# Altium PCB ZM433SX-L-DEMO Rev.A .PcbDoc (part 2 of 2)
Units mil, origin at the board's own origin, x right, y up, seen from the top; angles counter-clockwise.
Board outline 3937.01 x 2559.06 mil, 2 copper layers (Top Layer, Bottom Layer); 88 components, 121 nets, 406 pads, 438 vias.
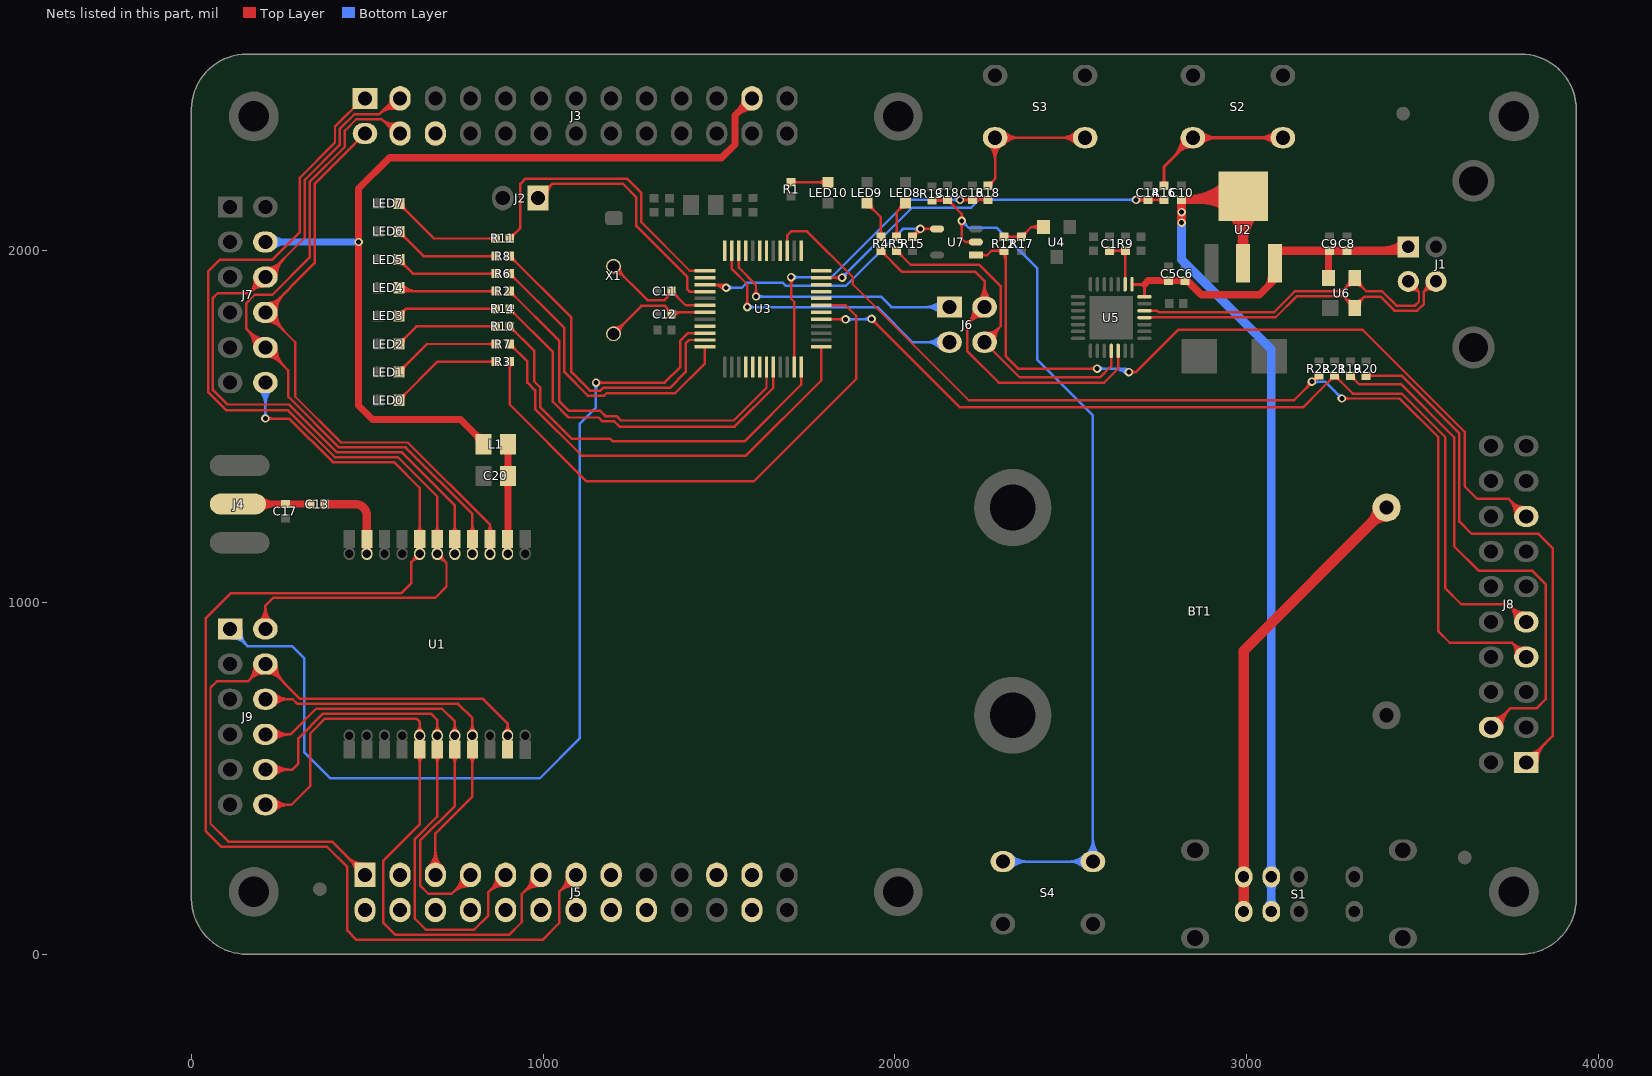
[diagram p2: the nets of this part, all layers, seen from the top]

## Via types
v1: diameter 24, hole 14, Top Layer to Bottom Layer, tented both sides, 426 vias
v2: diameter 20, hole 12, Top Layer to Bottom Layer, tented both sides, 7 vias
v3: diameter 24, hole 14, Top Layer to Bottom Layer, tented bottom, 5 vias

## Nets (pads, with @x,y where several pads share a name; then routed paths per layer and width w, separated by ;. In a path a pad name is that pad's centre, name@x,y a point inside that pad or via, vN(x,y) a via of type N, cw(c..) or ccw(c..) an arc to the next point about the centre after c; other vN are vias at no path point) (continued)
ESEL: J9.1 U3.10 | length 3069.9
  Top Layer w7: v1(1150,1624.91) 1345,1624.91 1390,1669.91 1390,1744.91 1411.1,1766.01 U3.10@1459.65,1766.01 ; v1@1156.01,1618.9 cw(c1170.52,1604.39) 1170.52,1624.91 cw(c1170.52,1645.43) v1@1156.01,1630.92
  Bottom Layer w7: J9.1@110,924.91 159,875.91 286,875.91 320,841.91 320,574.91 395,499.91 990,499.91 1104.5,614.41 1104.5,1508.41 1150,1553.91 v1(1150,1624.91) ; J9.1@115,898.41 cw(c115,846.5) 151.7,883.2 ; J9.1@115,905.41 cw(c115,870.4) J9.1@139.75,895.15 ; J9.1@127.47,924.01 ccw(c161.33,921.59) J9.1@137.32,897.58 ; J9.1@134.45,923.51 ccw(c181.55,920.14) 148.16,886.75 ; J9.1@141.43,923.01 ccw(c201.78,918.69) 159,875.91 ; v1@1143.99,1618.9 cw(c1129.48,1604.39) 1150,1604.39 cw(c1170.52,1604.39) v1@1156.01,1618.9
GPIO1_17: J5.14
GPIO1_18: J5.13 J7.12 U1.18 | length 4089.4
  Top Layer w7: v1(210,1523.03) 277.68,1523.03 401.8,1398.91 576,1398.91 648.72,1326.18 U1.18@648.72,1180.18 ; v1@216.01,1517.02 cw(c230.52,1502.51) 230.52,1523.03 cw(c230.52,1543.55) v1@216.01,1529.04 ; 628.8,1118.92 ccw(c610.87,1136.85) U1.18@636.22,1136.85 ; 636.43,1126.55 cw(c648.03,1114.96) U1.18@648.55,1131.35 ; U1.18@639.88,1198.61 ccw(c618.55,1219.95) 648.72,1219.95 ccw(c678.9,1219.95) U1.18@657.56,1198.61 ; U1.18@648.33,1124.35 ccw(c647.32,1092.81) 625,1115.12 ; U1.18@648.72,1138.85 625,1115.12 ; 1051.61,183.97 ccw(c1014.9,220.67) J5.13@1066.81,220.67 ; 1055.68,188.04 cw(c1087.92,155.8) J5.13@1091.69,201.24 ; 1063.56,195.92 ccw(c1038.8,220.67) J5.13@1073.81,220.67 ; 1066.35,198.72 cw(c1089.56,175.51) J5.13@1092.27,208.21 ; J5.13@1091.11,194.26 ccw(c1086.28,136.09) 1045,177.36 ; J5.13@1093.31,225.67 1045,177.36 ; 625,1115.12 625,1054.91 596.97,1026.88 111.97,1026.88 40,954.91 40,349.91 85,304.91 386,304.91 443,247.91 443,66.91 469,40.91 998,40.91 1045,87.91 1045,177.36
  Bottom Layer w7: J7.12@191.26,1606.17 cw(c146.02,1560.93) 210,1560.93 cw(c273.98,1560.93) J7.12@228.74,1606.17 ; J7.12@196.21,1611.12 cw(c162.92,1577.83) 210,1577.83 cw(c257.08,1577.83) J7.12@223.79,1611.12 ; J7.12@201.16,1616.07 cw(c179.82,1594.73) 210,1594.73 cw(c240.18,1594.73) J7.12@218.84,1616.07 ; v1@203.99,1529.04 ccw(c189.48,1543.55) 210,1543.55 ccw(c230.52,1543.55) v1@216.01,1529.04 ; v1(210,1523.03) J7.12@210,1624.91
GPIO2_4: J5.12
GPIO2_5: J5.11 J9.12 U1.5 | length 2310.9
  Top Layer w7: J9.12@210,424.91 284,424.91 337.5,478.41 337.5,627.41 380,669.91 640,669.91 648.72,661.18 U1.5@648.72,620.97 ; J9.12@223.84,416.07 cw(c245.18,394.73) 245.18,424.91 cw(c245.18,455.08) J9.12@223.84,433.75 ; J9.12@228.79,411.12 cw(c262.08,377.83) 262.08,424.91 cw(c262.08,471.98) J9.12@228.79,438.7 ; J9.12@233.74,406.17 cw(c278.98,360.93) 278.98,424.91 cw(c278.98,488.88) J9.12@233.74,443.65 ; U1.5@639.88,563.19 cw(c618.55,541.85) 648.72,541.85 cw(c678.9,541.85) U1.5@657.56,563.19 ; U1.5@639.88,631.81 ccw(c618.55,653.15) 648.72,653.15 ccw(c678.9,653.15) U1.5@657.56,631.81 ; U1.5@648.72,581.62 648.72,368.63 545,264.91 545,89.91 580,54.91 903,54.91 939,90.91 939,171.36 J5.11@993.31,225.67 ; 939.54,171.9 cw(c993.31,118.12) J5.11@993.31,194.17 ; 951.48,183.85 cw(c993.31,142.02) J5.11@993.31,201.17 ; 951.61,183.97 ccw(c914.9,220.67) J5.11@966.81,220.67 ; 963.43,195.8 cw(c993.31,165.92) J5.11@993.31,208.17 ; 963.56,195.92 ccw(c938.8,220.67) J5.11@973.81,220.67
GPIO2_6: J5.10
GPIO2_7: J5.9 J9.10 U1.6 | length 2038.4
  Top Layer w7: J9.10@210,524.91 287,524.91 304,541.91 304,613.71 374.2,683.91 681,683.91 698.72,666.18 U1.6@698.72,620.97 ; J9.10@223.84,516.07 cw(c245.18,494.73) 245.18,524.91 cw(c245.18,555.08) J9.10@223.84,533.75 ; J9.10@228.79,511.12 cw(c262.08,477.83) 262.08,524.91 cw(c262.08,571.98) J9.10@228.79,538.7 ; J9.10@233.74,506.17 cw(c278.98,460.93) 278.98,524.91 cw(c278.98,588.88) J9.10@233.74,543.65 ; U1.6@689.88,563.19 cw(c668.55,541.85) 698.72,541.85 cw(c728.9,541.85) U1.6@707.56,563.19 ; U1.6@689.88,631.81 ccw(c668.55,653.15) 698.72,653.15 ccw(c728.9,653.15) U1.6@707.56,631.81 ; U1.6@698.72,581.62 698.72,391.43 635,327.71 635,100.91 666,69.91 804,69.91 844,109.91 844,176.36 ; 851.61,183.97 ccw(c814.9,220.67) J5.9@866.81,220.67 ; 854.91,187.27 cw(c888.82,153.36) J5.9@892.01,201.21 ; 863.56,195.92 ccw(c838.8,220.67) J5.9@873.81,220.67 ; 865.82,198.18 cw(c890.19,173.81) J5.9@892.48,208.2 ; J5.9@891.55,194.23 ccw(c887.46,132.91) 844,176.36 ; J5.9@893.31,225.67 844,176.36
GPIO2_12: J5.8
GPIO2_13: J5.7 J9.8 U1.7 | length 1751.3
  Top Layer w7: J9.8@210,624.91 281,624.91 354,697.91 712,697.91 748.72,661.18 U1.7@748.72,620.97 ; J9.8@223.84,616.07 cw(c245.18,594.73) 245.18,624.91 cw(c245.18,655.08) J9.8@223.84,633.75 ; J9.8@228.79,611.12 cw(c262.08,577.83) 262.08,624.91 cw(c262.08,671.98) J9.8@228.79,638.7 ; J9.8@233.74,606.17 cw(c278.98,560.93) 278.98,624.91 cw(c278.98,688.88) J9.8@233.74,643.65 ; U1.7@739.88,563.19 cw(c718.55,541.85) 748.72,541.85 cw(c778.9,541.85) U1.7@757.56,563.19 ; U1.7@739.88,631.81 ccw(c718.55,653.15) 748.72,653.15 ccw(c778.9,653.15) U1.7@757.56,631.81 ; U1.7@748.72,581.62 748.72,421.63 650,322.91 650,194.91 673,171.91 739.55,171.91 ; 751.49,183.86 cw(c793.3,142.06) J5.7@793.31,201.17 ; 751.61,183.97 ccw(c714.9,220.67) J5.7@766.81,220.67 ; 763.44,195.8 cw(c793.3,165.94) J5.7@793.31,208.17 ; 763.56,195.92 ccw(c738.8,220.67) J5.7@773.81,220.67 ; J5.7@793.3,194.17 ccw(c793.29,118.17) 739.55,171.91 ; J5.7@793.31,225.67 739.55,171.91
GPIO2_14: J5.6
GPIO2_15: J5.5 J9.6 U1.8 | length 1599.3
  Top Layer w7: J9.6@210,724.91 288,724.91 301,711.91 758,711.91 798.72,671.18 U1.8@798.72,620.97 ; J9.6@223.84,716.07 cw(c245.18,694.73) 245.18,724.91 cw(c245.18,755.08) J9.6@223.84,733.75 ; J9.6@228.79,711.12 cw(c262.08,677.83) 262.08,724.91 cw(c262.08,771.98) J9.6@228.79,738.7 ; J9.6@233.74,706.17 cw(c278.98,660.93) 278.98,724.91 cw(c278.98,788.88) J9.6@233.74,743.65 ; J5.5@674.57,249.41 ccw(c629.33,294.65) 693.31,294.65 ccw(c757.29,294.65) J5.5@712.05,249.41 ; J5.5@679.52,244.46 ccw(c646.23,277.75) 693.31,277.75 ccw(c740.39,277.75) J5.5@707.1,244.46 ; J5.5@684.47,239.51 ccw(c663.13,260.85) 693.31,260.85 ccw(c723.49,260.85) J5.5@702.15,239.51 ; J5.5@693.31,225.67 693.31,343.22 798.72,448.63 U1.8@798.72,581.62 ; U1.8@789.88,563.19 cw(c768.55,541.85) 798.72,541.85 cw(c828.9,541.85) U1.8@807.56,563.19 ; U1.8@789.88,631.81 ccw(c768.55,653.15) 798.72,653.15 ccw(c828.9,653.15) U1.8@807.56,631.81
GPIO3_20: J5.4
GPIO3_21: J5.3
GPIO3_26: J5.2
GPIO3_27: J5.1 J9.4 U1.10 | length 2516.4
  Top Layer w7: 168.3,783.2 cw(c205,746.5) J9.4@205,798.41 ; 171.84,786.75 ccw(c138.45,820.14) J9.4@185.55,823.51 ; J9.4@178.57,823.01 cw(c118.22,818.69) 161,775.91 ; 180.25,795.15 cw(c205,770.4) J9.4@205,805.41 ; 182.68,797.58 ccw(c158.67,821.59) J9.4@192.53,824.01 ; J9.4@215,798.41 cw(c215,746.5) 251.7,783.2 ; J9.4@215,805.41 cw(c215,770.4) 239.75,795.15 ; J9.4@227.5,824.91 ccw(c269.75,824.91) 239.87,795.03 ; J9.4@234.5,824.91 ccw(c293.65,824.91) 251.82,783.08 ; J9.4@241.5,824.91 ccw(c317.55,824.91) 263.77,771.13 ; 439.54,279.44 ccw(c493.31,333.22) J5.1@493.31,257.17 ; 451.48,267.49 ccw(c493.31,309.32) J5.1@493.31,250.17 ; 451.61,267.37 cw(c414.9,230.67) J5.1@466.81,230.67 ; J5.1@463.43,255.54 ccw(c493.31,285.42) J5.1@493.31,243.17 ; J5.1@463.56,255.42 cw(c438.8,230.67) J5.1@473.81,230.67 ; J5.1@493.31,225.67 399.07,319.91 105,319.91 54,370.91 54,757.91 72,775.91 161,775.91 ; U1.10@889.88,631.81 ccw(c868.55,653.15) 898.72,653.15 ccw(c928.9,653.15) U1.10@907.56,631.81 ; U1.10@898.72,620.97 898.72,656.18 829,725.91 309,725.91 J9.4@210,824.91 161,775.91
HPL: J5.24
HPR: J5.23
HSADC: J5.18
I2C0_SCL: J5.15
I2C0_SDA: J5.16
J_NRST: J8.15 R12.1 U7.1 | length 2723.4
  Top Layer w7: U7.1@2230,1987.51 2262.6,1987.51 2275,1999.91 R12.1@2310,1999.91 2314.5,1995.41 2314.5,1700.41 2350,1664.91 v1(2575,1664.91) ; U7.1@2244.6,1982.91 cw(c2255.69,1971.81) 2255.69,1987.51 cw(c2255.69,2003.2) U7.1@2244.6,1992.1 ; R12.1@2303.14,1994.03 ccw(c2288.95,1979.84) 2288.95,1999.91 ccw(c2288.95,2019.97) R12.1@2303.14,2005.78 ; R12.1@2305.11,1994.03 cw(c2282.43,1971.35) 2314.5,1971.35 ; R12.1@2310.06,1998.98 cw(c2299.33,1988.25) R12.1@2314.5,1988.25 ; R12.1@2314.5,1988.33 cw(c2322.56,1988.33) R12.1@2316.86,1994.03 ; v1@2568.99,1658.9 ccw(c2554.48,1644.39) 2554.48,1664.91 ccw(c2554.48,1685.43) v1@2568.99,1670.92 ; v1(2665,1654.91) 2685,1654.91 ; v1@2671.12,1649.01 cw(c2685,1635.63) 2685,1654.91 ; v1@2671.12,1660.81 ccw(c2685,1674.18) 2685,1654.91 ; 3753.3,1286.61 ccw(c3790,1323.31) J8.15@3790,1271.41 ; 3756.07,1283.84 cw(c3720.98,1248.75) J8.15@3770.53,1245.99 ; J8.15@3763.54,1246.38 ccw(c3700.01,1249.91) 3745,1294.9 ; 3765.25,1274.66 ccw(c3790,1299.41) J8.15@3790,1264.41 ; 3767.14,1272.77 cw(c3741.95,1247.58) J8.15@3777.52,1245.6 ; J8.15@3795,1244.91 3745,1294.91 ; 2685,1654.91 2805,1774.91 3330,1774.91 3620,1484.91 3620,1329.91 3655,1294.91 3745,1294.91
  Bottom Layer w7: v1(2575,1664.91) 2655,1664.91 v1(2665,1654.91) ; v1@2581.01,1658.9 cw(c2595.52,1644.39) 2595.52,1664.91 cw(c2595.52,1685.43) v1@2581.01,1670.92 ; 2620.34,1664.91 cw(c2620.34,1610.24) v1@2658.99,1648.9 ; 2637.24,1664.91 cw(c2637.24,1627.14) v1@2663.94,1653.85 ; 2654.14,1664.91 cw(c2654.14,1644.04) v1@2668.89,1658.8
MIC: J5.21
NetC1_2: C1.2 R9.1 U5.9 | length 235.3
  Top Layer w7: C1.2@2610,1999.91 R9.1@2655,1999.91 2654.37,1999.28 U5.9@2654.37,1904.4 ; C1.2@2616.86,1994.03 cw(c2631.05,1979.84) 2631.05,1999.91 cw(c2631.05,2019.97) C1.2@2616.86,2005.78 ; R9.1@2648.14,2005.78 cw(c2633.95,2019.97) 2633.95,1999.91 cw(c2633.95,1979.84) 2648.14,1994.03 cw(c2633.1,1978.99) 2654.37,1978.99 ; 2654.37,1980.7 cw(c2673.22,1980.7) R9.1@2659.89,1994.03
NetC13_1: C13.1 U1.21 | length 247.3
  Top Layer w24: C13.1@378,1279.91 465,1279.91 cw(c465,1246.18) 498.72,1246.18 U1.21@498.72,1180.18 U1.21@498.72,1138.85
NetC13_2: C13.2 C17.1 J4.1 | length 282.5
  Top Layer w20: J4.1@132,1279.91 C17.1@267,1279.91 C13.2@338.63,1279.91 ; J4.1@196.14,1265.76 cw(c230.28,1231.62) 230.28,1279.91 cw(c230.28,1328.19) J4.1@196.14,1294.05
NetC18_1: C18.1 R13.2 S4.2 S4.3 U7.2 | length 3376.8
  Top Layer w7: R13.2@2105,2142.67 C18.1@2152.24,2142.67 ; R13.2@2111.86,2136.79 cw(c2126.05,2122.61) 2126.05,2142.67 cw(c2126.05,2162.74) R13.2@2111.86,2148.55 ; 2123.55,2142.67 ccw(c2123.55,2170.37) C18.1@2143.14,2150.78 ; 2134.35,2142.67 cw(c2134.35,2130.24) C18.1@2143.14,2139.03 ; C18.1@2150,2144.91 C18.1@2152.24,2142.67 ; C18.1@2150.98,2136.6 cw(c2150.98,2118.91) 2163.49,2131.42 ; C18.1@2159.3,2144.91 ccw(c2181.74,2144.91) 2165.87,2129.04 ; v1@2183.99,2078.9 cw(c2169.48,2064.39) 2190,2064.39 cw(c2210.52,2064.39) v1@2196.01,2078.9 ; v1@2184.1,2091.03 ccw(c2170.72,2104.91) 2190,2104.91 ; v1@2195.9,2091.03 cw(c2209.28,2104.91) 2190,2104.91 ; U7.2@2215.4,2020.31 ccw(c2204.31,2009.22) 2204.31,2024.91 ccw(c2204.31,2040.6) U7.2@2215.4,2029.5 ; U7.2@2230,2024.91 2200,2024.91 2190,2034.91 v1(2190,2084.91) 2190,2104.91 ; C18.1@2152.24,2142.67 2190,2104.91
  Bottom Layer w7: v1@2190,2076.41 cw(c2190,2055.89) 2204.51,2070.4 cw(c2219.02,2084.91) v1@2198.5,2084.91 ; v1(2190,2084.91) 2210,2064.91 2290,2064.91 2405,1949.91 2405,1689.91 2562.95,1531.95 S4.2@2562.95,263.49 S4.3@2307.05,263.49 ; S4.3@2320.89,254.65 cw(c2342.22,233.31) 2342.22,263.49 cw(c2342.22,293.67) S4.3@2320.89,272.33 ; S4.3@2325.84,249.7 cw(c2359.12,216.41) 2359.12,263.49 cw(c2359.12,310.57) S4.3@2325.84,277.28 ; S4.3@2330.79,244.75 cw(c2376.02,199.51) 2376.02,263.49 cw(c2376.02,327.47) S4.3@2330.79,282.23 ; S4.2@2539.21,244.75 ccw(c2493.98,199.51) 2493.98,263.49 ccw(c2493.98,327.47) S4.2@2539.21,282.23 ; S4.2@2544.16,249.7 ccw(c2510.88,216.41) 2510.88,263.49 ccw(c2510.88,310.57) S4.2@2544.16,277.28 ; S4.2@2544.21,282.23 ccw(c2498.98,327.47) 2562.95,327.47 ccw(c2626.93,327.47) S4.2@2581.69,282.23 ; S4.2@2549.11,254.65 ccw(c2527.78,233.31) 2527.78,263.49 ccw(c2527.78,293.67) S4.2@2549.11,272.33 ; S4.2@2549.16,277.28 ccw(c2515.88,310.57) 2562.95,310.57 ccw(c2610.03,310.57) S4.2@2576.74,277.28 ; S4.2@2554.11,272.33 ccw(c2532.78,293.67) 2562.95,293.67 ccw(c2593.13,293.67) S4.2@2571.79,272.33
NetC20_1: C20.1 L1.1 U1.13 | length 499.8
  Top Layer w20: C20.1@891.06,1345.07 cw(c869.49,1323.49) 900,1323.49 cw(c930.51,1323.49) C20.1@908.94,1345.07 ; C20.1@891.06,1374.75 ccw(c869.49,1396.32) 900,1396.32 ccw(c930.51,1396.32) C20.1@908.94,1374.75 ; L1.1@891.06,1435.07 cw(c869.49,1413.49) 900,1413.49 cw(c930.51,1413.49) L1.1@908.94,1435.07 ; U1.13@894.48,1145.09 ccw(c881.16,1158.41) U1.13@900,1158.41 ; U1.13@894.48,1166.35 cw(c881.16,1153.03) U1.13@900,1153.03 ; U1.13@894.48,1194.02 ccw(c881.16,1207.34) 900,1207.34 ; U1.13@898.72,1138.85 900,1140.12 C20.1@900,1359.91 L1.1@900,1449.91
NetJ1_2: J1.2 U5.5 U6.3 | length 1165.9
  Top Layer w7: U5.5@2709.49,1829.59 2745.31,1829.59 2750,1824.91 3076.92,1824.91 3136.92,1884.91 3269.5,1884.91 U6.3@3307.5,1922.91 3307.5,1917.41 3340,1884.91 3384.8,1884.91 3425.8,1843.91 3479,1843.91 3490,1854.91 3490,1882.27 J1.2@3459.57,1912.7 ; 3274.21,1889.62 cw(c3307.5,1856.33) 3307.5,1903.41 cw(c3307.5,1869.61) 3331.4,1893.51 ; 3286.16,1901.57 cw(c3307.5,1880.23) U6.3@3307.5,1910.41 ; 3286.28,1901.69 ccw(c3270.06,1917.91) U6.3@3293,1917.91 ; U6.3@3315,1917.91 ccw(c3334.31,1917.91) U6.3@3320.66,1904.25 ; U6.3@3322,1917.91 ccw(c3358.21,1917.91) 3332.61,1892.3 ; J1.2@3465.67,1894.18 cw(c3470.67,1879.02) 3481.96,1890.31 cw(c3493.25,1901.6) J1.2@3478.09,1906.6 ; J1.2@3467.86,1887.53 cw(c3474.66,1866.93) 3490,1882.27 cw(c3505.34,1897.61) J1.2@3484.73,1904.41
NetJ1_3: J1.3 U5.4 U6.2 | length 1200.5
  Top Layer w7: U5.4@2709.49,1809.91 2710.49,1810.91 3082.72,1810.91 3142.72,1870.91 3274,1870.91 U6.2@3307.5,1837.41 ; U5.4@2726.24,1808.9 cw(c2731.08,1804.06) 2731.08,1810.91 ; 3275.06,1869.84 ccw(c3307.5,1902.28) 3307.5,1856.41 ccw(c3307.5,1890.21) 3331.4,1866.31 ; 3285.93,1858.98 cw(c3268.86,1841.91) U6.2@3293,1841.91 ; 3287.01,1857.89 ccw(c3307.5,1878.38) U6.2@3307.5,1849.41 ; U6.2@3307.5,1836.91 U6.2@3307.5,1837.41 ; U6.2@3315,1841.91 cw(c3334.31,1841.91) U6.2@3320.66,1855.56 ; U6.2@3322,1841.91 cw(c3358.21,1841.91) 3332.61,1867.51 ; 3511.27,1891.17 cw(c3523.57,1878.87) J1.3@3530.52,1894.82 ; J1.3@3512.11,1908.68 cw(c3483.61,1904.3) 3504,1883.91 ; 3513.77,1893.68 ccw(c3500.55,1906.9) J1.3@3519.03,1909.74 ; J1.3@3527.73,1888.41 ccw(c3519.17,1868.74) 3504,1883.91 ; J1.3@3538.31,1912.7 3532.8,1912.7 3504,1883.91 ; U6.2@3307.5,1837.41 3307.5,1842.41 3335,1869.91 3380,1869.91 3420,1829.91 3485,1829.91 3504,1848.91 3504,1883.91
NetJ8_4: J8.4 R19.2 | length 1736.7
  Top Layer w7: R19.2@3295,1644.91 3320,1619.91 3440,1619.91 3590,1469.91 3590,1159.91 3659.5,1090.41 3811.78,1090.41 3850,1052.18 3850,724.91 3825,699.91 3750,699.91 J8.4@3695,644.91 ; R19.2@3295.98,1636.6 cw(c3295.98,1618.91) 3308.49,1631.42 ; R19.2@3304.3,1644.91 ccw(c3326.74,1644.91) 3310.87,1629.04 ; J8.4@3700,664.41 ccw(c3700,699.41) 3724.75,674.66 ; J8.4@3700,671.41 ccw(c3700,723.31) 3736.7,686.61 ; J8.4@3712.5,644.91 cw(c3754.75,644.91) 3724.87,674.78 ; J8.4@3719.5,644.91 cw(c3778.65,644.91) 3736.82,686.73 ; J8.4@3726.5,644.91 cw(c3802.55,644.91) 3748.77,698.68
NetLED0_2: LED0.2 R3.1 | length 399
  Top Layer w7: LED0.2@589.53,1574.91 699.53,1684.91 R3.1@865,1684.91 ; LED0.2@589.53,1587.15 ccw(c589.53,1616.72) 610.44,1595.82 ccw(c631.34,1574.91) LED0.2@601.78,1574.91 ; R3.1@859.12,1679.03 ccw(c844.94,1664.84) 844.94,1684.91 ccw(c844.94,1704.97) R3.1@859.12,1690.78
NetLED1_2: LED1.2 R7.2 | length 386.6
  Top Layer w7: LED1.2@589.53,1654.91 669.53,1734.91 R7.2@865,1734.91 ; LED1.2@589.53,1667.15 ccw(c589.53,1696.72) 610.44,1675.82 ccw(c631.34,1654.91) LED1.2@601.78,1654.91 ; R7.2@859.12,1729.03 ccw(c844.94,1714.84) 844.94,1734.91 ccw(c844.94,1754.97) R7.2@859.12,1740.78
NetLED2_2: LED2.2 R10.2 | length 374.1
  Top Layer w7: LED2.2@589.53,1734.91 639.53,1784.91 R10.2@865,1784.91 ; LED2.2@589.53,1747.15 ccw(c589.53,1776.72) 610.44,1755.82 ccw(c631.34,1734.91) LED2.2@601.78,1734.91 ; R10.2@859.12,1779.03 ccw(c844.94,1764.84) 844.94,1784.91 ccw(c844.94,1804.97) R10.2@859.12,1790.78
NetLED3_2: LED3.2 R14.2 | length 358.6
  Top Layer w7: LED3.2@589.53,1814.91 609.53,1834.91 ; LED3.2@589.92,1827.15 ccw(c590.77,1853.67) 609.53,1834.91 ; LED3.2@601.77,1815.3 cw(c628.29,1816.15) 609.53,1834.91 ; R14.2@859.12,1829.03 ccw(c844.94,1814.84) 844.94,1834.91 ccw(c844.94,1854.97) R14.2@859.12,1840.78 ; R14.2@865,1834.91 609.53,1834.91
NetLED4_2: LED4.2 R2.1 | length 421.4
  Top Layer w7: LED4.2@588.29,1893.67 ccw(c609.44,1914.82) 609.44,1884.91 ; LED4.2@589.53,1894.91 599.53,1884.91 R2.1@865,1884.91 ; LED4.2@593.24,1898.62 ccw(c626.34,1931.72) 626.34,1884.91 ; LED4.2@598.19,1903.57 ccw(c643.24,1948.62) 643.24,1884.91 ; R2.1@859.12,1879.03 ccw(c844.94,1864.84) 844.94,1884.91 ccw(c844.94,1904.97) R2.1@859.12,1890.78
NetLED5_2: LED5.2 R6.2 | length 370
  Top Layer w7: LED5.2@589.53,1962.66 cw(c589.53,1933.09) 610.44,1954 cw(c631.34,1974.91) LED5.2@601.78,1974.91 ; LED5.2@589.53,1974.91 629.53,1934.91 R6.2@865,1934.91 ; R6.2@859.12,1929.03 ccw(c844.94,1914.84) 844.94,1934.91 ccw(c844.94,1954.97) R6.2@859.12,1940.78
NetLED6_2: LED6.2 R8.2 | length 382.4
  Top Layer w7: LED6.2@589.53,2042.66 cw(c589.53,2013.09) 610.44,2034 cw(c631.34,2054.91) LED6.2@601.78,2054.91 ; LED6.2@589.53,2054.91 659.53,1984.91 R8.2@865,1984.91 ; R8.2@859.12,1979.03 ccw(c844.94,1964.84) 844.94,1984.91 ccw(c844.94,2004.97) R8.2@859.12,1990.78
NetLED7_2: LED7.2 R11.2 | length 394.9
  Top Layer w7: LED7.2@589.53,2122.66 cw(c589.53,2093.09) 610.44,2114 cw(c631.34,2134.91) LED7.2@601.78,2134.91 ; LED7.2@589.53,2134.91 689.53,2034.91 R11.2@865,2034.91 ; R11.2@859.12,2029.03 ccw(c844.94,2014.84) 844.94,2034.91 ccw(c844.94,2054.97) R11.2@859.12,2040.78
NetLED8_2: LED8.2 R5.2 | length 183.8
  Top Layer w7: R5.2@1999.12,2045.78 ccw(c1984.94,2059.97) 2005,2059.97 ccw(c2025.06,2059.97) R5.2@2010.88,2045.78 ; R5.2@2005,2039.91 2005,2110.38 LED8.2@2030,2135.38 ; LED8.2@2017.75,2135.38 cw(c1988.18,2135.38) 2009.09,2114.47 cw(c2030,2093.56) LED8.2@2030,2123.13
NetLED9_2: LED9.2 R4.2 | length 190
  Top Layer w7: LED9.2@1920,2123.13 cw(c1920,2093.56) 1940.91,2114.47 cw(c1961.82,2135.38) LED9.2@1932.25,2135.38 ; LED9.2@1920,2135.38 1960,2095.38 R4.2@1960,2039.91 ; R4.2@1954.12,2045.78 ccw(c1939.94,2059.97) 1960,2059.97 ccw(c1980.06,2059.97) R4.2@1965.88,2045.78
NetLED10_1: LED10.1 R1.1 | length 183.2
  Top Layer w7: R1.1@1705,2194.91 1705.47,2194.43 LED10.1@1810,2194.43 ; R1.1@1711.86,2189.03 cw(c1724.91,2175.98) 1724.91,2194.43 ; R1.1@1711.86,2200.78 ccw(c1727.19,2216.11) 1727.19,2194.43 ; LED10.1@1801.34,2185.77 ccw(c1780.43,2164.87) 1780.43,2194.43 ccw(c1780.43,2224) LED10.1@1801.34,2203.1
NetR12_2: R12.2 R17.1 U4.2 | length 302
  Top Layer w7: R12.2@2310,2039.91 R17.1@2360,2039.91 2387.5,2067.41 U4.2@2422.6,2067.41 ; R12.2@2316.86,2034.03 cw(c2331.05,2019.84) 2331.05,2039.91 cw(c2331.05,2059.97) R12.2@2316.86,2045.78 ; R17.1@2353.14,2034.03 ccw(c2338.95,2019.84) 2338.95,2039.91 ccw(c2338.95,2059.97) R17.1@2353.14,2045.78 ; R17.1@2360.98,2048.22 ccw(c2360.98,2065.91) 2373.49,2053.4 ; R17.1@2369.3,2039.91 cw(c2391.74,2039.91) 2375.87,2055.78 ; U4.2@2412.35,2057.15 ccw(c2387.59,2032.4) 2387.59,2067.41 ccw(c2387.59,2102.41) U4.2@2412.35,2077.66 ; U4.2@2417.29,2062.1 ccw(c2404.49,2049.3) 2404.49,2067.41 ccw(c2404.49,2085.51) U4.2@2417.29,2072.71
NetR16_1: R16.1 S2.2 S2.3 | length 931.9
  Top Layer w9: R16.1@2759.83,2190.08 ccw(c2747.35,2202.56) 2765,2202.56 ccw(c2782.65,2202.56) R16.1@2770.17,2190.08 ; R16.1@2765,2184.91 2765,2239.28 S2.2@2847.05,2321.32 S2.3@3102.95,2321.32 ; 2794.98,2269.26 ccw(c2742.91,2321.32) S2.2@2816.55,2321.32 ; 2807.05,2281.33 cw(c2842.05,2246.33) S2.2@2842.05,2295.82 ; 2810.34,2284.62 ccw(c2773.64,2321.32) S2.2@2825.55,2321.32 ; 2822.42,2296.69 cw(c2842.05,2277.06) S2.2@2842.05,2304.82 ; S2.2@2863.71,2309.66 cw(c2891.88,2281.49) 2891.88,2321.32 cw(c2891.88,2361.16) S2.2@2863.71,2332.99 ; S2.2@2870.08,2303.29 cw(c2913.61,2259.76) 2913.61,2321.32 cw(c2913.61,2382.89) S2.2@2870.08,2339.36 ; S2.3@3079.92,2303.29 ccw(c3036.39,2259.76) 3036.39,2321.32 ccw(c3036.39,2382.89) S2.3@3079.92,2339.36 ; S2.3@3086.29,2309.66 ccw(c3058.12,2281.49) 3058.12,2321.32 ccw(c3058.12,2361.16) S2.3@3086.29,2332.99
NetR18_2: R18.2 S3.2 S3.3 | length 1097.6
  Top Layer w7: R18.2@2265,2184.91 2284.73,2204.64 S3.2@2284.73,2321.32 S3.3@2540.64,2321.32 ; R18.2@2265.98,2193.22 ccw(c2265.98,2210.91) 2278.49,2198.4 ; S3.2@2266,2302.59 cw(c2220.76,2257.35) 2284.73,2257.35 cw(c2348.71,2257.35) S3.2@2303.47,2302.59 ; S3.2@2270.95,2307.54 cw(c2237.66,2274.25) 2284.73,2274.25 cw(c2331.81,2274.25) S3.2@2298.52,2307.54 ; R18.2@2274.3,2184.91 cw(c2296.74,2184.91) 2280.87,2200.78 ; S3.2@2275.89,2312.49 cw(c2254.56,2291.15) 2284.73,2291.15 cw(c2314.91,2291.15) S3.2@2293.57,2312.49 ; S3.2@2298.57,2312.49 cw(c2319.91,2291.15) 2319.91,2321.32 cw(c2319.91,2351.5) S3.2@2298.57,2330.16 ; S3.2@2303.52,2307.54 cw(c2336.81,2274.25) 2336.81,2321.32 cw(c2336.81,2368.4) S3.2@2303.52,2335.11 ; S3.2@2308.47,2302.59 cw(c2353.71,2257.35) 2353.71,2321.32 cw(c2353.71,2385.3) S3.2@2308.47,2340.06 ; S3.3@2516.9,2302.59 ccw(c2471.66,2257.35) 2471.66,2321.32 ccw(c2471.66,2385.3) S3.3@2516.9,2340.06 ; S3.3@2521.85,2307.54 ccw(c2488.56,2274.25) 2488.56,2321.32 ccw(c2488.56,2368.4) S3.3@2521.85,2335.11 ; S3.3@2526.8,2312.49 ccw(c2505.46,2291.15) 2505.46,2321.32 ccw(c2505.46,2351.5) S3.3@2526.8,2330.16
PIO0_0: R15.1 U3.3 U7.4 | length 1118.4
  Top Layer w7: U3.3@1459.65,1903.8 1511.1,1903.8 ; U3.3@1478,1903.8 cw(c1478,1852.91) v1@1513.99,1888.9 ; 1494.9,1903.8 cw(c1494.9,1869.8) v1@1518.94,1893.85 ; 1511.8,1903.8 cw(c1511.8,1886.7) v1@1523.89,1898.8 ; v1@1512.18,1898.24 ccw(c1507.52,1900.22) 1511.1,1903.8 ; v1@1516.67,1902.73 cw(c1514.68,1907.38) 1511.1,1903.8 ; v1(1520,1894.91) 1511.1,1903.8 ; R15.1@2050,2039.91 v1(2072.4,2062.31) U7.4@2120,2062.31 ; R15.1@2050.98,2048.22 ccw(c2050.98,2065.91) 2063.49,2053.4 ; R15.1@2053.93,2047.88 ccw(c2043.79,2065.44) v1@2063.95,2063.23 ; R15.1@2059.3,2039.91 cw(c2081.74,2039.91) v1@2065.87,2055.78 ; R15.1@2059.37,2044.52 cw(c2075.83,2035.02) v1@2073.46,2053.87 ; 2061.86,2052.46 ccw(c2058.97,2057.46) v1@2064.41,2059.42 ; 2062.96,2050.73 ccw(c2052.26,2056.91) v1@2064.19,2060.11 ; v1@2063.9,2062.31 cw(c2043.38,2062.31) 2057.89,2047.8 cw(c2072.4,2033.29) v1@2072.4,2053.81 ; v1@2078.41,2056.3 cw(c2092.92,2041.79) 2092.92,2062.31 cw(c2092.92,2082.83) v1@2078.41,2068.32 ; U7.4@2105.4,2057.71 ccw(c2094.31,2046.62) 2094.31,2062.31 ccw(c2094.31,2078) U7.4@2105.4,2066.9 ; 2063.08,2053.16 cw(c2067.77,2045.03) 2070.2,2054.1 ccw(c2067.77,2045.03) 2063.08,2053.16
  Bottom Layer w7: v1(1520,1894.91) 1565,1894.91 1578.5,1908.41 1681.5,1908.41 1690,1899.91 1860,1899.91 2022.4,2062.31 v1(2072.4,2062.31) ; v1@1526.01,1888.9 cw(c1540.52,1874.39) 1540.52,1894.91 cw(c1540.52,1915.43) v1@1526.01,1900.92 ; v1@2066.39,2056.3 ccw(c2051.88,2041.79) 2051.88,2062.31 ccw(c2051.88,2082.83) v1@2066.39,2068.32
PIO0_1: J2.1 U3.4 | length 821.7
  Top Layer w7: J2.1@985,2149.91 1026,2190.91 1226,2190.91 1265,2151.91 1265,2069.91 1410,1924.91 1410,1889.91 1415.79,1884.12 U3.4@1459.65,1884.12 ; J2.1@989.31,2173.92 ccw(c995.91,2203.05) 1017.03,2181.93 ; J2.1@990.86,2180.75 ccw(c999.22,2217.68) 1026,2190.91 ccw(c1061.01,2155.89) J2.1@1011.5,2155.25 ; J2.1@1004.5,2155.16 cw(c1037.84,2155.59) J2.1@1014.26,2179.17
PIO0_5: U3.16
PIO0_7: C16.2 R18.1 U3.23 | length 1133.8
  Top Layer w7: v1@1698.99,1918.9 cw(c1684.48,1904.39) 1705,1904.39 cw(c1725.52,1904.39) v1@1711.01,1918.9 ; v1(1705,1924.91) 1705,1863.49 1713.58,1854.91 U3.23@1713.58,1669.55 ; v1(2185,2144.91) C16.2@2220,2144.91 R18.1@2265,2144.91 ; v1@2191.01,2138.9 cw(c2205.52,2124.39) 2205.52,2144.91 cw(c2205.52,2165.43) v1@2191.01,2150.92 ; C16.2@2213.14,2139.03 ccw(c2198.95,2124.84) 2198.95,2144.91 ccw(c2198.95,2164.97) C16.2@2213.14,2150.78 ; C16.2@2226.86,2139.03 cw(c2241.05,2124.84) 2241.05,2144.91 cw(c2241.05,2164.97) C16.2@2226.86,2150.78 ; R18.1@2258.14,2139.03 ccw(c2243.95,2124.84) 2243.95,2144.91 ccw(c2243.95,2164.97) R18.1@2258.14,2150.78
  Bottom Layer w7: v1(1705,1924.91) 1820,1924.91 1827.5,1932.41 1827.5,1932.81 2039.6,2144.91 v1(2185,2144.91) ; v1@1711.01,1918.9 cw(c1725.52,1904.39) 1725.52,1924.91 cw(c1725.52,1945.43) v1@1711.01,1930.92 ; v1@2178.99,2138.9 ccw(c2164.48,2124.39) 2164.48,2144.91 ccw(c2164.48,2165.43) v1@2178.99,2150.92
PIO0_10: J8.9 R21.2 U3.29 | length 3073.8
  Top Layer w7: U3.29@1790.35,1805.38 v1@1859.53,1805.38 ; 1838.34,1805.38 cw(c1838.34,1783.25) v1@1853.99,1798.9 ; 1840.62,1805.38 ccw(c1840.62,1824.29) v1@1853.99,1810.92 ; v1@1933.5,1797.91 cw(c1933.5,1777.39) 1948.01,1791.9 cw(c1962.52,1806.41) v1@1942,1806.41 ; v1(1933.5,1806.41) 2185,1554.91 3160,1554.91 3210,1604.91 R21.2@3250.33,1645.2 3301.62,1593.91 3441,1593.91 3565,1469.91 3565,1039.91 3610,994.91 3745,994.91 ; 3234.46,1629.33 ccw(c3218.6,1645.2) R21.2@3241.04,1645.2 ; 3236.84,1631.71 cw(c3249.35,1619.2) R21.2@3249.35,1636.89 ; R21.2@3251.32,1636.89 cw(c3251.32,1619.2) 3263.82,1631.71 ; R21.2@3259.63,1645.2 ccw(c3282.07,1645.2) 3266.2,1629.33 ; 3753.3,986.61 ccw(c3790,1023.31) J8.9@3790,971.41 ; 3756.07,983.84 cw(c3720.98,948.75) J8.9@3770.53,945.99 ; J8.9@3763.54,946.38 ccw(c3700.01,949.91) 3745,994.9 ; 3765.25,974.66 ccw(c3790,999.41) J8.9@3790,964.41 ; 3767.14,972.77 cw(c3741.95,947.58) J8.9@3777.52,945.6 ; J8.9@3795,944.91 3745,994.91
  Bottom Layer w7: v1(1860,1804.91) 1932,1804.91 v1(1933.5,1806.41) ; v1@1866.01,1798.9 cw(c1880.52,1784.39) 1880.52,1804.91 cw(c1880.52,1825.43) v1@1866.01,1810.92 ; 1909.36,1804.91 ccw(c1909.36,1830.55) v1@1927.49,1812.42 ; 1916.6,1804.91 cw(c1916.6,1789.51) v1@1927.49,1800.4
PIO0_11: U3.32
PIO1_0: U3.33
PIO1_1: U3.34
PIO1_2: C14.1 R16.2 U3.35 | length 1289.8
  Top Layer w7: U3.35@1790.35,1923.49 v1(1850,1923.49) ; v1@1843.99,1917.48 ccw(c1829.48,1902.97) 1829.48,1923.49 ccw(c1829.48,1944.01) v1@1843.99,1929.5 ; v1(2685.67,2144.91) C14.1@2720,2144.91 R16.2@2765,2144.91 ; v1@2691.68,2138.9 cw(c2706.19,2124.39) 2706.19,2144.91 cw(c2706.19,2165.43) v1@2691.68,2150.92 ; C14.1@2713.14,2139.03 ccw(c2698.95,2124.84) 2698.95,2144.91 ccw(c2698.95,2164.97) C14.1@2713.14,2150.78 ; C14.1@2726.86,2139.03 cw(c2741.05,2124.84) 2741.05,2144.91 cw(c2741.05,2164.97) C14.1@2726.86,2150.78 ; R16.2@2758.14,2139.03 ccw(c2743.95,2124.84) 2743.95,2144.91 ccw(c2743.95,2164.97) R16.2@2758.14,2150.78
  Bottom Layer w7: v1(1850,1923.49) 2048.92,2122.41 2216.5,2122.41 2239,2144.91 v1(2685.67,2144.91) ; v1@1850,1931.99 ccw(c1850,1952.51) 1864.51,1938 ccw(c1879.02,1923.49) v1@1858.5,1923.49 ; v1@2679.66,2138.9 ccw(c2665.15,2124.39) 2665.15,2144.91 ccw(c2665.15,2165.43) v1@2679.66,2150.92
PIO1_3: J8.7 R22.2 U3.39 | length 3423.4
  Top Layer w7: U3.39@1693.9,2000.26 1693.9,2043.8 1705,2054.91 1750.4,2054.91 1880,1925.31 1880,1904.91 2210,1574.91 3135.04,1574.91 R22.2@3205.33,1645.2 ; 3169.52,1609.39 ccw(c3151.11,1627.8) v1@3177.15,1627.8 ; 3175.04,1614.9 cw(c3185.65,1604.29) v1@3185.65,1619.3 ; v1@3185.65,1636.3 ccw(c3185.65,1662.33) R22.2@3204.06,1643.92 ; v1@3186.85,1636.21 ccw(c3188.14,1645.2) R22.2@3196.01,1640.66 ; v1@3188.9,1635.65 ccw(c3193.68,1647.16) 3199.91,1636.37 ccw(c3205.74,1626.28) v1@3194.12,1627.16 ; v1@3189.46,1629.33 ccw(c3173.6,1645.2) R22.2@3196.04,1645.2 ; v1@3191.84,1631.71 cw(c3204.35,1619.2) R22.2@3204.35,1636.89 ; v1@3193.86,1630 cw(c3205.31,1633.06) R22.2@3195.04,1638.99 ; v1@3194.15,1627.8 cw(c3209.16,1627.8) R22.2@3198.54,1638.41 ; v1(3270.62,1579.91) 3435,1579.91 3545,1469.91 3545,917.91 3577.5,885.41 3754.5,885.41 ; v1@3276.63,1573.9 cw(c3291.14,1559.39) 3291.14,1579.91 cw(c3291.14,1600.43) v1@3276.63,1585.92 ; 3763.36,876.55 cw(c3742.93,856.12) J8.7@3771.03,849.43 ; J8.7@3764.22,851.05 ccw(c3728.63,859.53) 3754.5,885.41 ; 3766.08,873.82 ccw(c3788.85,896.58) J8.7@3789.56,864.4 ; J8.7@3789.41,871.4 cw(c3788.34,919.24) 3754.5,885.4 ; J8.7@3795,844.91 3754.5,885.41
  Bottom Layer w7: v1(3185.65,1627.8) 3222.73,1627.8 v1(3270.62,1579.91) ; v1@3191.66,1621.78 cw(c3206.17,1607.27) 3206.17,1627.8 cw(c3206.17,1648.32) v1@3191.66,1633.81 ; v1@3262.12,1579.91 ccw(c3241.6,1579.91) 3256.11,1594.42 ccw(c3270.62,1608.93) v1@3270.62,1588.41
PIO1_4: U3.40
PIO1_5: U3.45
PIO1_6: J6.1 U3.46 | length 999.3
  Top Layer w7: U3.46@1556.1,2000.26 1556.1,1951.8 1605,1902.91 v1(1605,1869.91) ; v1@1598.99,1875.92 ccw(c1584.48,1890.43) 1605,1890.43 ccw(c1625.52,1890.43) v1@1611.01,1875.92
  Bottom Layer w7: v1(1605,1869.91) 1960,1869.91 1990,1839.91 J6.1@2155,1839.91 ; v1@1611.01,1863.9 cw(c1625.52,1849.39) 1625.52,1869.91 cw(c1625.52,1890.43) v1@1611.01,1875.92 ; J6.1@2131.26,1821.17 ccw(c2086.02,1775.93) 2086.02,1839.91 ccw(c2086.02,1903.88) J6.1@2131.26,1858.65 ; J6.1@2136.21,1826.12 ccw(c2102.92,1792.83) 2102.92,1839.91 ccw(c2102.92,1886.98) J6.1@2136.21,1853.7 ; J6.1@2141.16,1831.07 ccw(c2119.82,1809.73) 2119.82,1839.91 ccw(c2119.82,1870.08) J6.1@2141.16,1848.75
PIO1_7: J6.3 U3.47 | length 1081.1
  Top Layer w7: U3.47@1536.42,2000.26 1536.42,1948.49 1580,1904.91 v1(1580,1839.91) ; v1@1573.99,1845.92 ccw(c1559.48,1860.43) 1580,1860.43 ccw(c1600.52,1860.43) v1@1586.01,1845.92
  Bottom Layer w7: v1(1580,1839.91) 1950,1839.91 2050,1739.91 J6.3@2155,1739.91 ; v1@1586.01,1833.9 cw(c1600.52,1819.39) 1600.52,1839.91 cw(c1600.52,1860.43) v1@1586.01,1845.92 ; J6.3@2131.26,1721.17 ccw(c2086.02,1675.93) 2086.02,1739.91 ccw(c2086.02,1803.88) J6.3@2131.26,1758.65 ; J6.3@2136.21,1726.12 ccw(c2102.92,1692.83) 2102.92,1739.91 ccw(c2102.92,1786.98) J6.3@2136.21,1753.7 ; J6.3@2141.16,1731.07 ccw(c2119.82,1709.73) 2119.82,1739.91 ccw(c2119.82,1770.08) J6.3@2141.16,1748.75
PIO1_8: U3.9
PIO1_9: U3.17
PIO1_10: U3.30
PIO1_11: U3.42
PIO2_0: U3.2
PIO2_4: R2.2 U3.19 | length 1111.8
  Top Layer w7: R2.2@905,1875.61 cw(c905,1853.17) 920.87,1869.04 ; R2.2@905,1884.91 1045,1744.91 1045,1573.09 1073.18,1544.91 1162,1544.91 1177,1529.91 1208.18,1529.91 1220.68,1517.41 1541.7,1517.41 1634.84,1610.55 U3.19@1634.84,1669.55 ; R2.2@913.31,1883.92 ccw(c931,1883.92) 918.49,1871.42
PIO2_5: R14.1 U3.20 | length 1107.7
  Top Layer w7: R14.1@905,1825.61 cw(c905,1803.17) 920.87,1819.04 ; R14.1@905,1834.91 1027.5,1712.41 1027.5,1570.79 1072.38,1525.91 1158,1525.91 1169,1514.91 1202,1514.91 1217,1499.91 1544,1499.91 1654.53,1610.43 U3.20@1654.53,1669.55 ; R14.1@913.31,1833.92 ccw(c931,1833.92) 918.49,1821.42
PIO2_6: R11.1 U3.1 | length 886.8
  Top Layer w7: R11.1@905,2034.91 935,2064.91 935,2189.91 950,2204.91 1238,2204.91 1279,2163.91 1279,2080.91 1416.73,1943.17 U3.1@1459.65,1943.17 ; R11.1@905,2044.2 ccw(c905,2066.64) 920.87,2050.78 ; R11.1@913.31,2035.89 cw(c931,2035.89) 918.49,2048.4
PIO2_7: R8.1 U3.11 | length 942.7
  Top Layer w7: R8.1@905,1975.61 cw(c905,1953.17) 920.87,1969.04 ; R8.1@905,1984.91 1080,1809.91 1080,1654.91 1132.5,1602.41 1162.5,1602.41 1170,1609.91 1360,1609.91 1405,1654.91 1405,1736.32 1415,1746.32 U3.11@1459.65,1746.32 ; R8.1@913.31,1983.92 ccw(c931,1983.92) 918.49,1971.42
PIO2_8: R6.1 U3.12 | length 887.8
  Top Layer w7: R6.1@905,1925.61 cw(c905,1903.17) 920.87,1919.04 ; R6.1@905,1934.91 1060,1779.91 1060,1654.91 1126.5,1588.41 1173.5,1588.41 1180,1594.91 1375,1594.91 1459.65,1679.55 U3.12@1459.65,1726.64 ; R6.1@913.31,1933.92 ccw(c931,1933.92) 918.49,1921.42
PIO2_9: R10.1 U3.24 | length 1196.3
  Top Layer w7: R10.1@905,1775.61 cw(c905,1753.17) 920.87,1769.04 ; R10.1@905,1784.91 974,1715.91 974,1629.09 991,1612.09 991,1555.63 1081.72,1464.91 1191.16,1464.91 1198.16,1457.91 1572,1457.91 1733.27,1619.17 U3.24@1733.27,1669.55 ; R10.1@913.31,1783.92 ccw(c931,1783.92) 918.49,1771.42
PIO2_10: R7.1 U3.25 | length 1298.6
  Top Layer w7: R7.1@905,1725.61 cw(c905,1703.17) 920.87,1719.04 ; R7.1@905,1734.91 955,1684.91 955,1624.91 977,1602.91 977,1549.83 1109.42,1417.41 1576.5,1417.41 1790.35,1631.26 U3.25@1790.35,1726.64 ; R7.1@913.31,1733.92 ccw(c931,1733.92) 918.49,1721.42
PIO2_11: R3.2 U3.31 | length 1641.1
  Top Layer w7: R3.2@899.12,1678.05 cw(c884.94,1663.86) 905,1663.86 cw(c925.06,1663.86) R3.2@910.88,1678.05 ; R3.2@905,1684.91 905,1562.43 1123.03,1344.41 1598.5,1344.41 1890,1635.91 1890,1814.91 1860.16,1844.75 U3.31@1790.35,1844.75
PIO3_0: U3.36
PIO3_1: U3.37
PIO3_2: U3.43
PIO3_3: U3.48
PIO3_4: U3.18
REG_OUT: C10.1 S1.3 S1.7 U2.2 U2.4 | length 3369.1
  Top Layer w25: v1(2815,2079.91) C10.1@2815,2144.91 2980,2144.91 U2.4@2990,2154.91 U2.2@2990,1964.91 ; C10.1@2827.04,2144.91 ccw(c2827.04,2317.87) U2.4@2949.34,2195.57 ; 2875.32,2144.91 cw(c2875.32,2040.23) 2949.34,2114.25 cw(c2851.18,2016.09) 2990,2016.09 cw(c3128.82,2016.09) U2.4@3030.66,2114.25 ; 2887.4,2144.91 ccw(c2887.4,2257.51) U2.4@2967.02,2177.89 ; U2.4@2967.02,2131.93 cw(c2911.54,2076.45) 2990,2076.45 cw(c3068.46,2076.45) U2.4@3012.98,2131.93 ; U2.2@2983.5,2003.66 ccw(c2955.44,2019.86) 2986.74,2028.25 ; 2993.26,2028.25 ccw(c3024.56,2019.86) U2.2@2996.5,2003.66
  Bottom Layer w25: v1(2815,2109.91) 2815,1974.91 3070,1719.91 S1.7@3070,219.91 S1.3@3070,121.48 ; S1.3@3061.16,135.32 ccw(c3039.82,156.66) 3070,156.66 ccw(c3100.18,156.66) S1.3@3078.84,135.32 ; S1.7@3061.16,206.07 cw(c3039.82,184.73) 3070,184.73 cw(c3100.18,184.73) S1.7@3078.84,206.07 ; S1.7@3061.16,233.75 ccw(c3039.82,255.08) 3070,255.08 ccw(c3100.18,255.08) S1.7@3078.84,233.75
RF_MISO: J3.4 J7.10 U1.15 | length 2505.3
  Top Layer w7: 156.23,1778.68 cw(c102.45,1724.91) J7.10@178.5,1724.91 ; 168.18,1766.73 cw(c126.35,1724.91) J7.10@185.5,1724.91 ; 168.3,1766.61 ccw(c205,1803.31) J7.10@205,1751.41 ; 180.13,1754.78 cw(c150.25,1724.91) J7.10@192.5,1724.91 ; 180.25,1754.66 ccw(c205,1779.41) J7.10@205,1744.41 ; J7.10@215,1698.41 cw(c215,1646.5) 251.7,1683.2 ; J7.10@215,1705.41 cw(c215,1670.4) 239.75,1695.15 ; J7.10@227.5,1724.91 ccw(c269.75,1724.91) 239.87,1695.03 ; J7.10@234.5,1724.91 ccw(c293.65,1724.91) 251.82,1683.08 ; J7.10@241.5,1724.91 ccw(c317.55,1724.91) 263.77,1671.13 ; 549.03,2365.88 ccw(c575.36,2392.21) J3.4@587.14,2356.89 ; 557.04,2357.87 ccw(c579.36,2380.2) J3.4@589.35,2350.24 ; 559.94,2354.96 cw(c543.36,2338.39) J3.4@566.81,2338.39 ; 565.04,2349.86 ccw(c583.37,2368.19) J3.4@591.57,2343.6 ; J3.4@584.92,2363.53 cw(c571.35,2404.22) 541.02,2373.89 ; J3.4@593.31,2333.39 581.52,2333.39 541.02,2373.89 ; U1.15@789.88,1198.61 ccw(c768.55,1219.95) 798.72,1219.95 ccw(c828.9,1219.95) U1.15@807.56,1198.61 ; U1.15@798.72,1180.18 798.72,1251.18 609,1440.91 419.2,1440.91 275,1585.11 275,1659.91 J7.10@210,1724.91 155.5,1779.41 155.5,1850.41 180,1874.91 230,1874.91 336,1980.91 336,2195.88 436,2295.88 436,2341.31 468.58,2373.89 541.02,2373.89
RF_MOSI: J3.3 J7.6 U1.16 | length 2703.4
  Top Layer w7: 168.3,1883.2 cw(c205,1846.5) J7.6@205,1898.41 ; 174.52,1889.43 ccw(c146.79,1917.17) J7.6@185.67,1922.34 ; J7.6@178.73,1921.41 cw(c129.1,1914.82) 164.5,1879.41 ; 180.25,1895.15 cw(c205,1870.4) J7.6@205,1905.41 ; 184.54,1899.45 ccw(c164.48,1919.52) J7.6@192.61,1923.26 ; J7.6@215,1944.41 ccw(c215,1979.41) 239.75,1954.66 ; J7.6@215,1951.41 ccw(c215,2003.31) 251.7,1966.61 ; J7.6@227.5,1924.91 cw(c269.75,1924.91) 239.87,1954.78 ; J7.6@234.5,1924.91 cw(c293.65,1924.91) 251.82,1966.73 ; J7.6@241.5,1924.91 cw(c317.55,1924.91) 263.77,1978.68 ; 541.9,2396.61 cw(c576.56,2361.95) J3.3@588.54,2409.48 ; 550.63,2405.33 cw(c580.07,2375.89) J3.3@590.25,2416.27 ; 559.35,2414.05 cw(c583.59,2389.82) J3.3@591.96,2423.05 ; 561.95,2416.66 ccw(c550.22,2428.39) J3.3@566.81,2428.39 ; J3.3@586.83,2402.69 ccw(c573.05,2348.02) 533.18,2387.89 ; J3.3@593.31,2433.39 578.68,2433.39 533.18,2387.89 ; U1.16@739.88,1198.61 ccw(c718.55,1219.95) 748.72,1219.95 ccw(c778.9,1219.95) U1.16@757.56,1198.61 ; U1.16@748.72,1180.18 748.72,1276.18 598,1426.91 413.4,1426.91 277.4,1562.91 102,1562.91 61,1603.91 61,1865.91 74.5,1879.41 164.5,1879.41 ; 164.5,1879.41 J7.6@210,1924.91 322,2036.91 322,2201.68 422,2301.68 422,2347.11 462.78,2387.89 533.18,2387.89
RF_SCK: J3.2 J7.8 U1.14 | length 2109.1
  Top Layer w7: J7.8@215,1798.41 cw(c215,1746.5) 251.7,1783.2 ; J7.8@215,1805.41 cw(c215,1770.4) 239.75,1795.15 ; J7.8@215,1844.41 ccw(c215,1879.41) 239.75,1854.66 ; J7.8@215,1851.41 ccw(c215,1903.31) 251.7,1866.61 ; 239.87,1795.03 cw(c269.75,1824.91) 227.5,1824.91 cw(c269.75,1824.91) 239.87,1854.78 ; 251.82,1783.08 cw(c293.65,1824.91) 234.5,1824.91 cw(c293.65,1824.91) 251.82,1866.73 ; 263.77,1771.13 cw(c317.55,1824.91) 241.5,1824.91 cw(c317.55,1824.91) 263.77,1878.68 ; J3.2@493.31,2333.39 350,2190.08 350,1964.91 J7.8@210,1824.91 295,1739.91 295,1584.91 425,1454.91 615,1454.91 848.72,1221.18 U1.14@848.72,1180.18 ; U1.14@839.88,1198.61 ccw(c818.55,1219.95) 848.72,1219.95 ccw(c878.9,1219.95) U1.14@857.56,1198.61
RF_SEL: J3.1 J9.2 U1.17 | length 3045
  Top Layer w7: J9.2@191.26,943.65 ccw(c146.02,988.88) 210,988.88 ccw(c273.98,988.88) J9.2@228.74,943.65 ; J9.2@196.21,938.7 ccw(c162.92,971.98) 210,971.98 ccw(c257.08,971.98) J9.2@223.79,938.7 ; J9.2@201.16,933.75 ccw(c179.82,955.08) 210,955.08 ccw(c240.18,955.08) J9.2@218.84,933.75 ; J9.2@210,924.91 210,990.91 231.97,1012.88 692.97,1012.88 725,1044.91 725,1112.57 U1.17@698.72,1138.85 ; J3.1@493.31,2433.39 488.48,2433.39 408,2352.91 408,2307.47 308,2207.47 308,2052.91 230,1974.91 81,1974.91 47,1940.91 47,1598.11 99.2,1545.91 274.6,1545.91 407.6,1412.91 587,1412.91 698.72,1301.18 U1.17@698.72,1180.18 ; U1.17@689.88,1198.61 ccw(c668.55,1219.95) 698.72,1219.95 ccw(c728.9,1219.95) U1.17@707.56,1198.61 ; U1.17@698.72,1124.35 cw(c698.72,1089.34) 723.48,1114.09 ; U1.17@698.72,1131.35 cw(c698.72,1113.24) 711.53,1126.04 ; U1.17@711.22,1136.85 ccw(c736.57,1136.85) 718.65,1118.92
RF_VCC: J3.23 J7.4 L1.2 | length 2757.9
  Top Layer w20: 806.88,1478.03 ccw(c830,1501.15) L1.2@830,1468.45 ; L1.2@809.07,1475.84 cw(c789.04,1455.81) L1.2@817.36,1455.81 ; L1.2@830,1449.91 830,1454.91 765,1519.91 515,1519.91 475,1559.91 v1(475,2024.91) 475,2176.63 562.78,2264.41 1507,2264.41 1545,2302.41 1545,2385.08 J3.23@1593.31,2433.39 ; 1550.63,2390.71 cw(c1593.31,2348.03) J3.23@1593.31,2408.39 ; 1562.7,2402.78 ccw(c1537.1,2428.39) J3.23@1573.31,2428.39
  Bottom Layer w20: J7.4@210,2024.91 v1(475,2024.91) ; J7.4@229.14,2010.76 cw(c263.28,1976.62) 263.28,2024.91 cw(c263.28,2073.19) J7.4@229.14,2039.05
RUN: J3.6
RXD: J6.4 R5.1 U5.25 | length 1181.4
  Top Layer w7: R5.1@2005,1999.91 2045,1959.91 2240,1959.91 2300.5,1899.41 2300.5,1785.41 J6.4@2255,1739.91 2355,1639.91 2583,1639.91 2615,1671.91 U5.25@2615,1715.42 ; R5.1@2005.98,1991.6 cw(c2005.98,1973.91) 2018.49,1986.42 ; R5.1@2014.3,1999.91 ccw(c2036.74,1999.91) 2020.87,1984.04 ; J6.4@2260,1759.41 ccw(c2260,1794.41) 2284.75,1769.66 ; J6.4@2260,1766.41 ccw(c2260,1818.31) 2296.7,1781.61 ; J6.4@2272.39,1741.55 cw(c2300.52,1745.29) 2280.46,1765.36 ; J6.4@2279.33,1742.48 cw(c2318.21,1747.65) 2290.48,1775.38 ; J6.4@2286.27,1743.4 cw(c2335.9,1750) 2300.5,1785.41
TXD: J6.2 R4.1 U5.26 | length 1531.4
  Top Layer w7: R4.1@1960,1999.91 2020,1939.91 2229,1939.91 2255,1913.91 J6.2@2255,1839.91 2205,1789.91 ; R4.1@1960.98,1991.6 cw(c1960.98,1973.91) 1973.49,1986.42 ; R4.1@1969.3,1999.91 ccw(c1991.74,1999.91) 1975.87,1984.04 ; 2213.3,1798.2 cw(c2250,1761.5) J6.2@2250,1813.41 ; 2216.07,1800.98 ccw(c2180.98,1836.07) J6.2@2230.53,1838.82 ; J6.2@2223.54,1838.44 cw(c2160.01,1834.9) 2205,1789.91 ; 2225.25,1810.15 cw(c2250,1785.4) J6.2@2250,1820.41 ; 2227.14,1812.05 ccw(c2201.95,1837.24) J6.2@2237.52,1839.21 ; J6.2@2236.26,1858.65 ccw(c2191.02,1903.88) 2255,1903.88 ccw(c2318.98,1903.88) J6.2@2273.74,1858.65 ; J6.2@2241.21,1853.7 ccw(c2207.92,1886.98) 2255,1886.98 ccw(c2302.08,1886.98) J6.2@2268.79,1853.7 ; J6.2@2246.16,1848.75 ccw(c2224.82,1870.08) 2255,1870.08 ccw(c2285.18,1870.08) J6.2@2263.84,1848.75 ; U5.26@2634.68,1715.42 2634.68,1664.59 2595,1624.91 2295,1624.91 2205,1714.91 2205,1789.91
VCC_BT: BT1.1 S1.4 S1.8 | length 1411.7
  Top Layer w30: S1.4@2991.26,121.48 S1.8@2991.26,219.91 2991.26,863.17 BT1.1@3397.99,1269.91 ; BT1.1@3372.99,1269.91 cw(c3312.64,1269.91) 3355.31,1227.23 cw(c3397.99,1184.55) BT1.1@3397.99,1244.91
VDD5: C5.1 C6.1 C8.2 C9.1 J1.1 U2.3 U5.7 U5.8 U6.4 | length 1163.8
  Top Layer w9: U5.8@2674.06,1904.4 2709.49,1904.4 U5.7@2709.49,1868.96
  Top Layer w20: 2709.49,1904.4 2720,1914.91 2831.01,1914.91 2871.01,1874.91 3037,1874.91 3080,1917.91 U2.3@3080,1964.91 ; C6.1@2824.98,1913.1 cw(c2824.98,1894.17) 2838.37,1907.55 ; 3054.44,1892.35 ccw(c3016.89,1929.91) U2.3@3070,1929.91 ; U6.4@3226.84,1933.56 ccw(c3213.19,1947.22) 3232.5,1947.22 ccw(c3251.81,1947.22) U6.4@3238.16,1933.56 ; U6.4@3232.5,1922.91 C9.1@3232.5,1996.88 ; J1.1@3448.66,2000.22 J1.1@3459.57,2011.13
  Top Layer w25: U2.3@3080,1964.91 3080,1989.91 3090.31,2000.22 3189.62,2000.22 C9.1@3235.84,2000.22 J1.1@3448.66,2000.22 ; 3390.98,2000.22 ccw(c3390.98,2079.72) J1.1@3447.19,2023.5
VT: J8.1 R20.2 | length 1759.6
  Top Layer w7: R20.2@3340,1644.91 3440,1644.91 3605,1479.91 3605,1229.91 3640,1194.91 3830,1194.91 3870,1154.91 3870,619.91 J8.1@3795,544.91 ; R20.2@3346.86,1639.03 cw(c3361.05,1624.84) 3361.05,1644.91 cw(c3361.05,1664.97) R20.2@3346.86,1650.78 ; J8.1@3800,564.41 ccw(c3800,599.41) J8.1@3824.75,574.66 ; J8.1@3800,571.41 ccw(c3800,623.31) 3836.7,586.61 ; J8.1@3812.5,544.91 cw(c3854.75,544.91) J8.1@3824.87,574.78 ; J8.1@3819.5,544.91 cw(c3878.65,544.91) 3836.82,586.73 ; J8.1@3826.5,544.91 cw(c3902.55,544.91) 3848.77,598.68
XTALIN: C11.1 U3.6 X1.2 | length 498.6
  Top Layer w7: X1.2@1200,1938.47 cw(c1200,1896.22) 1229.87,1926.1 cw(c1259.75,1955.97) X1.2@1217.5,1955.97 ; X1.2@1200,1945.47 cw(c1200,1920.12) 1217.92,1938.05 cw(c1235.85,1955.97) X1.2@1210.5,1955.97 ; X1.2@1200,1955.97 1296.06,1859.91 1345,1859.91 1365,1879.91 C11.1@1365,1884.91 1405.16,1844.75 U3.6@1459.65,1844.75 ; 1347.97,1862.88 ccw(c1326.93,1883.92) C11.1@1356.69,1883.92 ; C11.1@1357.67,1872.57 cw(c1365,1865.24) 1365,1875.61 cw(c1365,1853.17) 1380.87,1869.04 ; C11.1@1373.31,1883.92 ccw(c1391,1883.92) 1378.49,1871.42
XTALOUT: C12.1 U3.7 X1.1 | length 485.6
  Top Layer w7: X1.1@1200,1763.84 1279.36,1843.2 1346.7,1843.2 1365,1824.91 C12.1@1365,1819.91 1370.16,1825.06 U3.7@1459.65,1825.06 ; X1.1@1200,1774.34 ccw(c1200,1799.69) 1217.92,1781.77 ccw(c1235.85,1763.84) X1.1@1210.5,1763.84 ; X1.1@1200,1781.34 ccw(c1200,1823.59) 1229.87,1793.72 ccw(c1259.75,1763.84) X1.1@1217.5,1763.84 ; 1347.97,1841.93 cw(c1326.93,1820.89) C12.1@1356.69,1820.89 ; C12.1@1357.67,1832.24 ccw(c1365,1839.57) C12.1@1365,1829.2 ; C12.1@1365.93,1819.96 cw(c1378.24,1807.65) 1378.24,1825.06 ; C12.1@1370.88,1815.01 cw(c1395.14,1790.75) 1395.14,1825.06
pads on no net: BT1.0 HOLE1.1 HOLE2.1 HOLE3.1 HOLE4.1 J3.20 J3.22 J3.25 J5.26 J8.2 J8.3 J8.5 J8.11 J8.13 J8.17 J8.19 MARK1.0 MARK2.0 MARK3.0 S1.0 S1.1 S1.5 U1.9 U5.1 U5.2 U5.10 U5.11 U5.12 U5.13 U5.14 U5.15 U5.16 U5.17 U5.18 U5.19 U5.20 U5.21 U5.22 U5.23 U5.24 U5.27 U5.28

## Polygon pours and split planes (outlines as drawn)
AGND on Bottom Layer "S2-No Net" (solid, remove dead copper, pour order 5): 0,157.48 ccw(c157.48,157.48) 157.48,0 3779.52,0 ccw(c3779.52,157.48) 3937,157.48 3937.01,157.48 3937.01,2401.52 ccw(c3779.53,2401.52) 3779.53,2559 3779.53,2559.06 157.48,2559.06 ccw(c157.48,2401.58) 0,2401.58
AGND on Top Layer "S2-No Net" (solid, remove dead copper, pour order 3): 0,157.48 ccw(c157.48,157.48) 157.48,0 3779.52,0 ccw(c3779.52,157.48) 3937,157.48 3937.01,157.48 3937.01,2401.52 ccw(c3779.53,2401.52) 3779.53,2559 3779.53,2559.06 157.48,2559.06 ccw(c157.48,2401.58) 0,2401.58

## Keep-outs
Keep-Out Layer:
  lines w5: 0,1139.91 38,1139.91 39,1140.91 39,1416.91 37,1418.91 0,1418.91 0,1405.91 ; 3779.53,2559 cw(c3779.53,2401.52) 3937.01,2401.52 3937.01,157.48 cw(c3779.52,157.48) 3779.52,0 157.48,0 cw(c157.48,157.48) 0,157.48 0,2401.58 cw(c157.48,2401.58) 157.48,2559.06 3779.53,2559.06

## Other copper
Top Layer:
  region net AGND: 211.27,1224.91 69.83,1224.91 59,1214.08 59,1129.91 68,1120.91 213.27,1120.91 237.27,1144.91 237.27,1210.91 221.27,1226.91 211.27,1226.91
  region net AGND: 211.27,1444.91 69.83,1444.91 59,1434.08 59,1349.91 68,1340.91 213.27,1340.91 237.27,1364.91 237.27,1430.91 221.27,1446.91 211.27,1446.91

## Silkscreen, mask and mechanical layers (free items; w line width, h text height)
Top Overlay:
  text "ISP" at 1060,2128.91 h40
  text "GND" at 293,2096.91 h40
  text "VCC" at 297,2006.91 h40
  text "MOSI" at 295,1910.91 h40
  text "MRXD" at 1923,1821.91 h40
  text "UTXD" at 2340,1817.91 h40
  text "SCK" at 294,1810.91 h40
  text "URXD" at 2341,1724.91 h40
  text "MTXD" at 1922,1713.91 h40
  text "MISO" at 295,1708.91 h40
  text "CSEL" at 293,1599.91 h40
  text "P/N :1.14.24.0084" at 1382.54,1250.54 h78.74
  text "DCEL" at 282,907.91 h35
  text "PLL" at 281,804.91 h40
  text "DAT" at 281,704.16 h40
  text "CLK" at 281,603.41 h40
  text "IRQ1" at 281,502.66 h40
  text "ZM433SX-L-DEMO" at 423,427.91 h90
  text "IRQ0" at 281,401.91 h40
  text "160401 Rev.A" at 504,334.91 h78.74
  text "BAT" at 3519,117.91 h40 r90
  text "USB" at 3585,117.91 h40 r90
  text "OFF" at 3647,113.91 h40 r90
Mechanical 1:
  lines w5: 3779.53,2559 cw(c3779.53,2401.52) 3937.01,2401.52 3937.01,157.48 cw(c3779.52,157.48) 3779.52,0 157.48,0 cw(c157.48,157.48) 0,157.48 0,1140.91 38,1140.91 38,1418.91 0,1418.91 0,2401.58 cw(c157.48,2401.58) 157.48,2559.06 3779.53,2559.06
Mechanical 2:
  circle w5: c177.17,177.17 r62.99
  circle w5: c177.17,177.17 r62.99
Mechanical 3:
  circle w6: c2009.45,2381.89 r98.43
  circle w6: c2009.45,177.17 r98.43
  circle w6: c3759.84,2381.89 r98.43
  circle w6: c3759.84,177.17 r98.43
  circle w6: c177.17,2381.89 r98.43
  circle w6: c177.17,177.17 r98.43
Drill Drawing:
  text ".Legend" at 3983.62,14.91 h36

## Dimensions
0,2401.58 to 3937.01,2401.52 on Mechanical 1
157.48,0 to 157.48,2559.06 on Mechanical 1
